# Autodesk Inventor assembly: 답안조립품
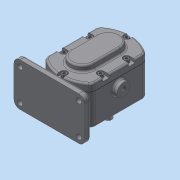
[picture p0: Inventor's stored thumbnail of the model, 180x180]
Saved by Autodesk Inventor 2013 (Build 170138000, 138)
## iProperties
Created: 2019-03
Part Number: 답안조립품
Document SubType Name: Assembly
Designer: dgall
Author: dgall
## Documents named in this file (11)
- C:\Users\dgall\Desktop\490307V1022\답안조립품.iam
- C:\Users\dgall\Desktop\490307V1022\본체.ipt
- C:\Users\dgall\Desktop\490307V1022\메인축.ipt
- C:\Users\dgall\Desktop\490307V1022\키 6 x 6 x 18.ipt
- C:\Users\dgall\Desktop\490307V1022\베어링부시.ipt
- C:\Users\dgall\Desktop\490307V1022\커버.ipt
- C:\Users\dgall\Desktop\490307V1022\볼트 M5.ipt
- C:\Users\dgall\Desktop\490307V1022\오일 실 16 28 7.ipt
- C:\Users\dgall\Desktop\490307V1022\서브축.ipt
- C:\Users\dgall\Desktop\490307V1022\스퍼기어.ipt
- C:\Users\dgall\Desktop\490307V1022\개스킷.ipt
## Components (1 placed, 1 different names)
1. 개스킷:1
